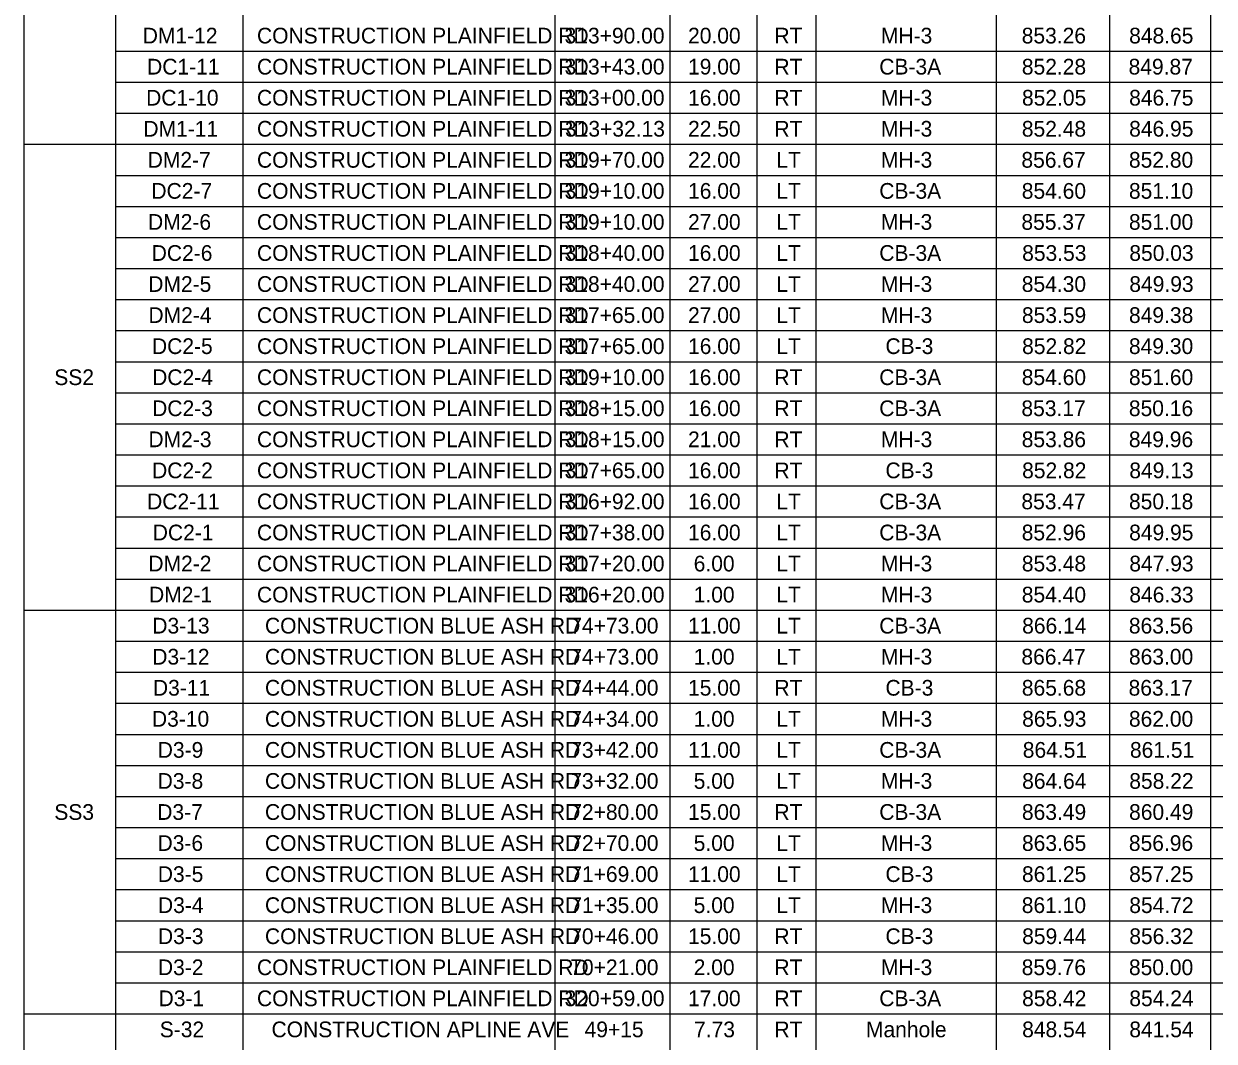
# Model space of a CAD drawing. Extents: x 0 to 34, y 0 to 22.
# Drawn here: x 12.9 to 20.28, y 9.39 to 15.7 of the extents above; entities that cross this region are included whole.
import ezdxf

# ---------------------------------------------------------------- set-up
doc = ezdxf.new("R2010")
doc.units = 0
doc.layers.add('SH_Text', color=7, linetype='Continuous')

msp = doc.modelspace()

# ---------------------------------------------------------------- linework, layer by layer
at = {"layer": 'SH_Text'}
for p, q in [((12.8973, 21.5), (12.8973, 0.4995)), ((13.4656, 21.3073), (13.4656, 0.4995)), ((14.2555, 21.3073), (14.2555, 0.4995)), ((16.1918, 21.3073), (16.1918, 0.4995)), ((16.9047, 21.3073), (16.9047, 0.4995)), ((17.4442, 21.3073), (17.4442, 0.4995)), ((17.8102, 21.3073), (17.8102, 0.4995)), ((18.9277, 21.3073), (18.9277, 0.4995)), ((19.6309, 21.3073), (19.6309, 0.4995)), ((20.2571, 21.3073), (20.2571, 0.4995)), ((13.4656, 15.5274), (29.6013, 15.5274)), ((13.4656, 15.3347), (29.6013, 15.3347)), ((13.4656, 15.1421), (29.6013, 15.1421)), ((12.8973, 14.9494), (29.6013, 14.9494)), ((13.4656, 14.7567), (29.6013, 14.7567)), ((13.4656, 14.5641), (29.6013, 14.5641)), ((13.4656, 14.3714), (29.6013, 14.3714)), ((13.4656, 14.1787), (29.6013, 14.1787)), ((13.4656, 13.9861), (29.6013, 13.9861)), ((13.4656, 13.7934), (29.6013, 13.7934)), ((13.4656, 13.6007), (29.6013, 13.6007)), ((13.4656, 13.4081), (29.6013, 13.4081)), ((13.4656, 13.2154), (29.6013, 13.2154)), ((13.4656, 13.0227), (29.6013, 13.0227)), ((13.4656, 12.8301), (29.6013, 12.8301)), ((13.4656, 12.6374), (29.6013, 12.6374)), ((13.4656, 12.4447), (29.6013, 12.4447)), ((13.4656, 12.2521), (29.6013, 12.2521)), ((12.8973, 12.0594), (29.6013, 12.0594)), ((13.4656, 11.8667), (29.6013, 11.8667)), ((13.4656, 11.6741), (29.6013, 11.6741)), ((13.4656, 11.4814), (29.6013, 11.4814)), ((13.4656, 11.2888), (29.6013, 11.2888)), ((13.4656, 11.0961), (29.6013, 11.0961)), ((13.4656, 10.9034), (29.6013, 10.9034)), ((13.4656, 10.7108), (29.6013, 10.7108)), ((13.4656, 10.5181), (29.6013, 10.5181)), ((13.4656, 10.3254), (29.6013, 10.3254)), ((13.4656, 10.1328), (29.6013, 10.1328)), ((13.4656, 9.9401), (29.6013, 9.9401)), ((13.4656, 9.7474), (29.6013, 9.7474)), ((12.8973, 9.5548), (29.6013, 9.5548))]:
    msp.add_line(p, q, dxfattribs=at)

# ---------------------------------------------------------------- texts
for s, height, p in [('DM1-12', 0.09749, (13.635, 15.575)), ('CONSTRUCTION PLAINFIELD RD', 0.097489, (14.3435, 15.575)), ('313+90.00', 0.09749, (16.2514, 15.575)), ('20.00', 0.09749, (17.0171, 15.575)), ('RT', 0.09749, (17.5529, 15.575)), ('MH-3', 0.09749, (18.2131, 15.575)), ('853.26', 0.09749, (19.0866, 15.575)), ('848.65', 0.09749, (19.7529, 15.575)), ('DC1-11', 0.09749, (13.662, 15.3823)), ('CONSTRUCTION PLAINFIELD RD', 0.097489, (14.3435, 15.3823)), ('313+43.00', 0.09749, (16.2514, 15.3823)), ('19.00', 0.09749, (17.0171, 15.3823)), ('RT', 0.09749, (17.5529, 15.3823)), ('CB-3A', 0.09749, (18.2031, 15.3823)), ('852.28', 0.09749, (19.0873, 15.3823)), ('849.87', 0.09749, (19.7494, 15.3823)), ('DC1-10', 0.09749, (13.6559, 15.1896)), ('CONSTRUCTION PLAINFIELD RD', 0.097489, (14.3435, 15.1896)), ('313+00.00', 0.09749, (16.2514, 15.1896)), ('16.00', 0.09749, (17.0171, 15.1896)), ('RT', 0.09749, (17.5529, 15.1896)), ('MH-3', 0.09749, (18.2131, 15.1896)), ('852.05', 0.09749, (19.0882, 15.1896)), ('846.75', 0.09749, (19.7529, 15.1896)), ('DM1-11', 0.09749, (13.6391, 14.997)), ('CONSTRUCTION PLAINFIELD RD', 0.097489, (14.3435, 14.997)), ('313+32.13', 0.09749, (16.2538, 14.997)), ('22.50', 0.09749, (17.0171, 14.997)), ('RT', 0.09749, (17.5529, 14.997)), ('MH-3', 0.09749, (18.2131, 14.997)), ('852.48', 0.09749, (19.0873, 14.997)), ('846.95', 0.09749, (19.7529, 14.997)), ('DM2-7', 0.09749, (13.6657, 14.8043)), ('CONSTRUCTION PLAINFIELD RD', 0.097489, (14.3435, 14.8043)), ('319+70.00', 0.09749, (16.2514, 14.8043)), ('22.00', 0.09749, (17.0171, 14.8043)), ('LT', 0.09749, (17.565, 14.8043)), ('MH-3', 0.09749, (18.2131, 14.8043)), ('856.67', 0.09749, (19.0847, 14.8043)), ('852.80', 0.09749, (19.7516, 14.8043)), ('DC2-7', 0.09749, (13.6887, 14.6116)), ('CONSTRUCTION PLAINFIELD RD', 0.097489, (14.3435, 14.6116)), ('319+10.00', 0.09749, (16.2514, 14.6116)), ('16.00', 0.09749, (17.0171, 14.6116)), ('LT', 0.09749, (17.565, 14.6116)), ('CB-3A', 0.09749, (18.2031, 14.6116)), ('854.60', 0.09749, (19.0869, 14.6116)), ('851.10', 0.09749, (19.7516, 14.6116)), ('DM2-6', 0.09749, (13.6676, 14.419)), ('CONSTRUCTION PLAINFIELD RD', 0.097489, (14.3435, 14.419)), ('319+10.00', 0.09749, (16.2514, 14.419)), ('27.00', 0.09749, (17.0171, 14.419)), ('LT', 0.09749, (17.565, 14.419)), ('MH-3', 0.09749, (18.2131, 14.419)), ('855.37', 0.09749, (19.0847, 14.419)), ('851.00', 0.09749, (19.7516, 14.419)), ('DC2-6', 0.09749, (13.6905, 14.2263)), ('CONSTRUCTION PLAINFIELD RD', 0.097489, (14.3435, 14.2263)), ('318+40.00', 0.09749, (16.2514, 14.2263)), ('16.00', 0.09749, (17.0171, 14.2263)), ('LT', 0.09749, (17.565, 14.2263)), ('CB-3A', 0.09749, (18.2031, 14.2263)), ('853.53', 0.09749, (19.0893, 14.2263)), ('850.03', 0.09749, (19.754, 14.2263)), ('DM2-5', 0.09749, (13.6692, 14.0337)), ('CONSTRUCTION PLAINFIELD RD', 0.097489, (14.3435, 14.0337)), ('318+40.00', 0.09749, (16.2514, 14.0337)), ('27.00', 0.09749, (17.0171, 14.0337)), ('LT', 0.09749, (17.565, 14.0337)), ('MH-3', 0.09749, (18.2131, 14.0337)), ('854.30', 0.09749, (19.0869, 14.0337)), ('849.93', 0.09749, (19.754, 14.0337)), ('DM2-4', 0.09749, (13.6703, 13.841)), ('CONSTRUCTION PLAINFIELD RD', 0.097489, (14.3435, 13.841)), ('317+65.00', 0.09749, (16.2514, 13.841)), ('27.00', 0.09749, (17.0171, 13.841)), ('LT', 0.09749, (17.565, 13.841)), ('MH-3', 0.09749, (18.2131, 13.841)), ('853.59', 0.09749, (19.0878, 13.841)), ('849.38', 0.09749, (19.752, 13.841)), ('DC2-5', 0.09749, (13.6922, 13.6483)), ('CONSTRUCTION PLAINFIELD RD', 0.097489, (14.3435, 13.6483)), ('317+65.00', 0.09749, (16.2514, 13.6483)), ('16.00', 0.09749, (17.0171, 13.6483)), ('LT', 0.09749, (17.565, 13.6483)), ('CB-3', 0.09749, (18.2415, 13.6483)), ('852.82', 0.09749, (19.089, 13.6483)), ('849.30', 0.09749, (19.7516, 13.6483)), ('SS2', 0.09749, (13.0862, 13.4557)), ('DC2-4', 0.09749, (13.6933, 13.4557)), ('CONSTRUCTION PLAINFIELD RD', 0.097489, (14.3435, 13.4557)), ('319+10.00', 0.09749, (16.2514, 13.4557)), ('16.00', 0.09749, (17.0171, 13.4557)), ('RT', 0.09749, (17.5529, 13.4557)), ('CB-3A', 0.09749, (18.2031, 13.4557)), ('854.60', 0.09749, (19.0869, 13.4557)), ('851.60', 0.09749, (19.7516, 13.4557)), ('DC2-3', 0.09749, (13.6933, 13.263)), ('CONSTRUCTION PLAINFIELD RD', 0.097489, (14.3435, 13.263)), ('318+15.00', 0.09749, (16.2514, 13.263)), ('16.00', 0.09749, (17.0171, 13.263)), ('RT', 0.09749, (17.5529, 13.263)), ('CB-3A', 0.09749, (18.2031, 13.263)), ('853.17', 0.09749, (19.0847, 13.263)), ('850.16', 0.09749, (19.7512, 13.263)), ('DM2-3', 0.09749, (13.6703, 13.0703)), ('CONSTRUCTION PLAINFIELD RD', 0.097489, (14.3435, 13.0703)), ('318+15.00', 0.09749, (16.2514, 13.0703)), ('21.00', 0.09749, (17.0171, 13.0703)), ('RT', 0.09749, (17.5529, 13.0703)), ('MH-3', 0.09749, (18.2131, 13.0703)), ('853.86', 0.09749, (19.0866, 13.0703)), ('849.96', 0.09749, (19.7512, 13.0703)), ('DC2-2', 0.09749, (13.693, 12.8777)), ('CONSTRUCTION PLAINFIELD RD', 0.097489, (14.3435, 12.8777)), ('317+65.00', 0.09749, (16.2514, 12.8777)), ('16.00', 0.09749, (17.0171, 12.8777)), ('RT', 0.09749, (17.5529, 12.8777)), ('CB-3', 0.09749, (18.2415, 12.8777)), ('852.82', 0.09749, (19.089, 12.8777)), ('849.13', 0.09749, (19.754, 12.8777)), ('DC2-11', 0.09749, (13.662, 12.685)), ('CONSTRUCTION PLAINFIELD RD', 0.097489, (14.3435, 12.685)), ('316+92.00', 0.09749, (16.2514, 12.685)), ('16.00', 0.09749, (17.0171, 12.685)), ('LT', 0.09749, (17.565, 12.685)), ('CB-3A', 0.09749, (18.2031, 12.685)), ('853.47', 0.09749, (19.0847, 12.685)), ('850.18', 0.09749, (19.752, 12.685)), ('DC2-1', 0.09749, (13.6971, 12.4923)), ('CONSTRUCTION PLAINFIELD RD', 0.097489, (14.3435, 12.4923)), ('317+38.00', 0.09749, (16.2514, 12.4923)), ('16.00', 0.09749, (17.0171, 12.4923)), ('LT', 0.09749, (17.565, 12.4923)), ('CB-3A', 0.09749, (18.2031, 12.4923)), ('852.96', 0.09749, (19.0866, 12.4923)), ('849.95', 0.09749, (19.7529, 12.4923)), ('DM2-2', 0.09749, (13.67, 12.2997)), ('CONSTRUCTION PLAINFIELD RD', 0.097489, (14.3435, 12.2997)), ('317+20.00', 0.09749, (16.2514, 12.2997)), ('6.00', 0.09749, (17.0521, 12.2997)), ('LT', 0.09749, (17.565, 12.2997)), ('MH-3', 0.09749, (18.2131, 12.2997)), ('853.48', 0.09749, (19.0873, 12.2997)), ('847.93', 0.09749, (19.754, 12.2997)), ('DM2-1', 0.09749, (13.6741, 12.107)), ('CONSTRUCTION PLAINFIELD RD', 0.097489, (14.3435, 12.107)), ('316+20.00', 0.09749, (16.2514, 12.107)), ('1.00', 0.09749, (17.0521, 12.107)), ('LT', 0.09749, (17.565, 12.107)), ('MH-3', 0.09749, (18.2131, 12.107)), ('854.40', 0.09749, (19.0869, 12.107)), ('846.33', 0.09749, (19.754, 12.107)), ('D3-13', 0.09749, (13.6944, 11.9143)), ('CONSTRUCTION BLUE ASH RD', 0.097489, (14.393, 11.9143)), ('74+73.00', 0.09749, (16.2864, 11.9143)), ('11.00', 0.09749, (17.0171, 11.9143)), ('LT', 0.09749, (17.565, 11.9143)), ('CB-3A', 0.09749, (18.2031, 11.9143)), ('866.14', 0.09749, (19.0893, 11.9143)), ('863.56', 0.09749, (19.7512, 11.9143)), ('D3-12', 0.09749, (13.6941, 11.7217)), ('CONSTRUCTION BLUE ASH RD', 0.097489, (14.393, 11.7217)), ('74+73.00', 0.09749, (16.2864, 11.7217)), ('1.00', 0.09749, (17.0521, 11.7217)), ('LT', 0.09749, (17.565, 11.7217)), ('MH-3', 0.09749, (18.2131, 11.7217)), ('866.47', 0.09749, (19.0847, 11.7217)), ('863.00', 0.09749, (19.7516, 11.7217)), ('D3-11', 0.09749, (13.6982, 11.529)), ('CONSTRUCTION BLUE ASH RD', 0.097489, (14.393, 11.529)), ('74+44.00', 0.09749, (16.2864, 11.529)), ('15.00', 0.09749, (17.0171, 11.529)), ('RT', 0.09749, (17.5529, 11.529)), ('CB-3', 0.09749, (18.2415, 11.529)), ('865.68', 0.09749, (19.0873, 11.529)), ('863.17', 0.09749, (19.7494, 11.529)), ('D3-10', 0.09749, (13.692, 11.3363)), ('CONSTRUCTION BLUE ASH RD', 0.097489, (14.393, 11.3363)), ('74+34.00', 0.09749, (16.2864, 11.3363)), ('1.00', 0.09749, (17.0521, 11.3363)), ('LT', 0.09749, (17.565, 11.3363)), ('MH-3', 0.09749, (18.2131, 11.3363)), ('865.93', 0.09749, (19.0893, 11.3363)), ('862.00', 0.09749, (19.7516, 11.3363)), ('D3-9', 0.09749, (13.7279, 11.1437)), ('CONSTRUCTION BLUE ASH RD', 0.097489, (14.393, 11.1437)), ('73+42.00', 0.09749, (16.2864, 11.1437)), ('11.00', 0.09749, (17.0171, 11.1437)), ('LT', 0.09749, (17.565, 11.1437)), ('CB-3A', 0.09749, (18.2031, 11.1437)), ('864.51', 0.09749, (19.0931, 11.1437)), ('861.51', 0.09749, (19.7578, 11.1437)), ('D3-8', 0.09749, (13.7274, 10.951)), ('CONSTRUCTION BLUE ASH RD', 0.097489, (14.393, 10.951)), ('73+32.00', 0.09749, (16.2864, 10.951)), ('5.00', 0.09749, (17.0521, 10.951)), ('LT', 0.09749, (17.565, 10.951)), ('MH-3', 0.09749, (18.2131, 10.951)), ('864.64', 0.09749, (19.0893, 10.951)), ('858.22', 0.09749, (19.7537, 10.951)), ('SS3', 0.09749, (13.0864, 10.7583)), ('D3-7', 0.09749, (13.7249, 10.7583)), ('CONSTRUCTION BLUE ASH RD', 0.097489, (14.393, 10.7583)), ('72+80.00', 0.09749, (16.2864, 10.7583)), ('15.00', 0.09749, (17.0171, 10.7583)), ('RT', 0.09749, (17.5529, 10.7583)), ('CB-3A', 0.09749, (18.2031, 10.7583)), ('863.49', 0.09749, (19.0878, 10.7583)), ('860.49', 0.09749, (19.7525, 10.7583)), ('D3-6', 0.09749, (13.7267, 10.5657)), ('CONSTRUCTION BLUE ASH RD', 0.097489, (14.393, 10.5657)), ('72+70.00', 0.09749, (16.2864, 10.5657)), ('5.00', 0.09749, (17.0521, 10.5657)), ('LT', 0.09749, (17.565, 10.5657)), ('MH-3', 0.09749, (18.2131, 10.5657)), ('863.65', 0.09749, (19.0882, 10.5657)), ('856.96', 0.09749, (19.7512, 10.5657)), ('D3-5', 0.09749, (13.7284, 10.373)), ('CONSTRUCTION BLUE ASH RD', 0.097489, (14.393, 10.373)), ('71+69.00', 0.09749, (16.2864, 10.373)), ('11.00', 0.09749, (17.0171, 10.373)), ('LT', 0.09749, (17.565, 10.373)), ('CB-3', 0.09749, (18.2415, 10.373)), ('861.25', 0.09749, (19.0882, 10.373)), ('857.25', 0.09749, (19.7529, 10.373)), ('D3-4', 0.09749, (13.7294, 10.1804)), ('CONSTRUCTION BLUE ASH RD', 0.097489, (14.393, 10.1804)), ('71+35.00', 0.09749, (16.2864, 10.1804)), ('5.00', 0.09749, (17.0521, 10.1804)), ('LT', 0.09749, (17.565, 10.1804)), ('MH-3', 0.09749, (18.2131, 10.1804)), ('861.10', 0.09749, (19.0869, 10.1804)), ('854.72', 0.09749, (19.7537, 10.1804)), ('D3-3', 0.09749, (13.7294, 9.9877)), ('CONSTRUCTION BLUE ASH RD', 0.097489, (14.393, 9.9877)), ('70+46.00', 0.09749, (16.2864, 9.9877)), ('15.00', 0.09749, (17.0171, 9.9877)), ('RT', 0.09749, (17.5529, 9.9877)), ('CB-3', 0.09749, (18.2415, 9.9877)), ('859.44', 0.09749, (19.0893, 9.9877)), ('856.32', 0.09749, (19.7537, 9.9877)), ('D3-2', 0.09749, (13.7291, 9.795)), ('CONSTRUCTION PLAINFIELD RD', 0.097489, (14.3435, 9.795)), ('70+21.00', 0.09749, (16.2864, 9.795)), ('2.00', 0.09749, (17.0521, 9.795)), ('MH-3', 0.09749, (18.2131, 9.795)), ('859.76', 0.09749, (19.0866, 9.795)), ('850.00', 0.09749, (19.7516, 9.795)), ('RT', 0.09749, (17.5529, 9.795)), ('D3-1', 0.09749, (13.7332, 9.6024)), ('CONSTRUCTION PLAINFIELD RD', 0.097489, (14.3435, 9.6024)), ('320+59.00', 0.09749, (16.2514, 9.6024)), ('17.00', 0.09749, (17.0171, 9.6024)), ('RT', 0.09749, (17.5529, 9.6024)), ('CB-3A', 0.09749, (18.2031, 9.6024)), ('858.42', 0.09749, (19.089, 9.6024)), ('854.24', 0.09749, (19.754, 9.6024)), ('S-32', 0.09749, (13.7404, 9.4097)), ('CONSTRUCTION APLINE AVE', 0.097489, (14.4337, 9.4097)), ('49+15', 0.09749, (16.3753, 9.4097)), ('7.73', 0.09749, (17.0544, 9.4097)), ('RT', 0.09749, (17.5529, 9.4097)), ('Manhole', 0.09749, (18.1206, 9.4097)), ('848.54', 0.09749, (19.0893, 9.4097)), ('841.54', 0.09749, (19.754, 9.4097))]:
    msp.add_text(s, height=height, dxfattribs=at).set_placement(p)

doc.saveas('drawing.dxf')
